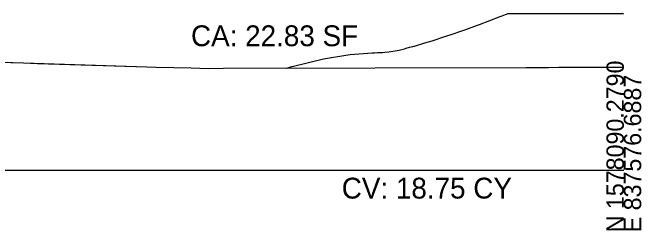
# Model space of a CAD drawing. Extents: x -26 to 303, y -16 to 6048.
# Drawn here: x 201.3 to 302.8, y 1990.3 to 2025.4 of the extents above; entities that cross this region are included whole.
import ezdxf

# ---------------------------------------------------------------- set-up
doc = ezdxf.new("R2010")
doc.units = 0
for name, color, linetype in [('DTM_P_FINISHED_GRADE', 7, 'Continuous'), ('DTM_TEMP_DROP', 7, 'Continuous'), ('DTM_X_FLOW_ARROWS', 7, 'Continuous'), ('DTM_X_GROUND', 7, 'Continuous'), ('XS_CELL', 7, 'Continuous'), ('XS_P_GROUND', 7, 'Continuous'), ('XS_SHEET_EW_TX_AREA', 7, 'Continuous'), ('XS_SHEET_EW_TX_VOLUME', 7, 'Continuous')]:
    doc.layers.add(name, color=color, linetype=linetype)

msp = doc.modelspace()

# ---------------------------------------------------------------- linework, layer by layer
at = {"layer": 'DTM_P_FINISHED_GRADE'}
msp.add_lwpolyline([(281.32, 2025.3), (288.59, 2025.3), (289.16, 2025.3), (291.3, 2025.3), (293.2, 2025.3), (293.33, 2025.3), (299.72, 2025.3)], dxfattribs=at)
at = {"layer": 'DTM_X_GROUND'}
for points in [[(181.76, 2017.96), (203.12, 2017.31), (223.02, 2016.67), (224.48, 2016.64), (227.35, 2016.56), (230.17, 2016.49), (232.95, 2016.42), (235.36, 2016.44), (284.26, 2016.56), (286.08, 2016.58), (287.82, 2016.59), (289.5, 2016.6), (291.11, 2016.61), (292.66, 2016.63), (294.16, 2016.64), (295.51, 2016.63), (297, 2016.63), (300, 2016.63)], [(196.9, 2017.5), (203.12, 2017.31), (205.34, 2017.24), (223.02, 2016.67), (224.48, 2016.64), (227.35, 2016.56), (230.17, 2016.49), (232.95, 2016.42), (235.36, 2016.44), (284.26, 2016.56), (286.08, 2016.58), (287.82, 2016.59), (289.5, 2016.6), (291.11, 2016.61), (292.66, 2016.63), (294.16, 2016.64), (295.51, 2016.63), (297, 2016.63), (300, 2016.63)]]:
    msp.add_lwpolyline(points, dxfattribs=at)
at = {"layer": 'XS_CELL'}
msp.add_line((150, 2000), (300, 2000), dxfattribs=at)
at = {"layer": 'XS_P_GROUND'}
for points in [[(245.62, 2016.47), (246.39, 2016.72), (246.44, 2016.73), (251.52, 2017.98), (255.47, 2018.62), (255.83, 2018.67), (259.38, 2018.91), (259.77, 2018.94), (260.24, 2018.96), (261.04, 2019), (261.4, 2019.04), (262.05, 2019.11), (262.41, 2019.16), (263.11, 2019.26), (263.11, 2019.26), (263.71, 2019.37), (264.61, 2019.6), (264.89, 2019.68), (265.43, 2019.82), (265.92, 2019.95), (266.08, 2020), (266.21, 2020.03), (267.89, 2020.53), (269.09, 2020.88), (271.29, 2021.6), (272.14, 2021.88), (274.02, 2022.54), (274.5, 2022.71), (276.39, 2023.4), (276.7, 2023.52), (280.05, 2024.8), (280.18, 2024.85), (281.32, 2025.3)], [(300, 2025.18), (299.72, 2025.3)]]:
    msp.add_lwpolyline(points, dxfattribs=at)

# ---------------------------------------------------------------- texts
at = {"layer": 'DTM_TEMP_DROP'}
for p in [(281.24, 2025.18), (299.64, 2025.18)]:
    msp.add_text('X', height=0.24, dxfattribs=at).set_placement(p)
at = {"layer": 'DTM_X_FLOW_ARROWS'}
msp.add_text('X', height=0.24, dxfattribs=at).set_placement((245.54, 2016.35))
at = {"layer": 'XS_CELL'}
for s, p in [('N 1578090.2790', (300, 1990)), ('E 837576.6887', (302.8, 1990))]:
    msp.add_text(s, height=2.8, rotation=90, dxfattribs=at).set_placement(p)
at = {"layer": 'XS_SHEET_EW_TX_AREA'}
msp.add_text('CA: 22.83 SF', height=3.36, dxfattribs=at).set_placement((230.14, 2020))
at = {"layer": 'XS_SHEET_EW_TX_VOLUME'}
msp.add_text('CV: 18.75 CY', height=3.36, dxfattribs=at).set_placement((254.47, 1995.44))

doc.saveas('drawing.dxf')
